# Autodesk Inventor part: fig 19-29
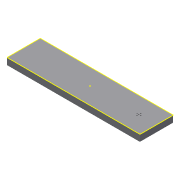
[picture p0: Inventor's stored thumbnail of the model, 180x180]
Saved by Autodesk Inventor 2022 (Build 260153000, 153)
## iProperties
Created: 2013-07
Part Number: fig 19-29
Material: Generic
Document SubType Name: Modeling
Designer: CADCIM
Density: 1 g/cm^3
Appearance: Default
Author: CADCIM
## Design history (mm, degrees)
sketch "Sketch1"
  geometry: L1 (-20, 5)-(20, 5); L2 (20, 5)-(20, -5); L3 (20, -5)-(-20, -5); L4 (-20, -5)-(-20, 5); L5 (-20, 5)-(20, -5); L6 (20, 5)-(-20, -5); 1 further point
  constraints: 12 end point, 2 midpoint, 2 parallel, 1 horizontal, 1 perpendicular
  dimensions: "d0" = 40 distance of L2.end L3.end; "d1" = 10 distance of L1.end L2.end
extrude "Extrusion1" new body sketch "Sketch1" distance "d2" = 2; taper "d3" = 0 deg
sketch "Sketch2"
  geometry: L1 (20, 5)-(-20, 5) reference; L2 (-20, 5)-(-20, -5) reference; L3 (-20, -5)-(20, -5) reference; L4 (20, -5)-(20, 5) reference; 2 further points
body "Solid1"
